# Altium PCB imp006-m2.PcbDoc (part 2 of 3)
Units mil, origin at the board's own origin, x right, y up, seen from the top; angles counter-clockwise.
Board outline 1181.1 x 1515.75 mil, 4 copper layers (Top Layer, Signal Layer 1, Signal Layer 2, Bottom Layer), stack 31.759 mil thick; 78 components, 116 nets, 508 pads, 482 vias.
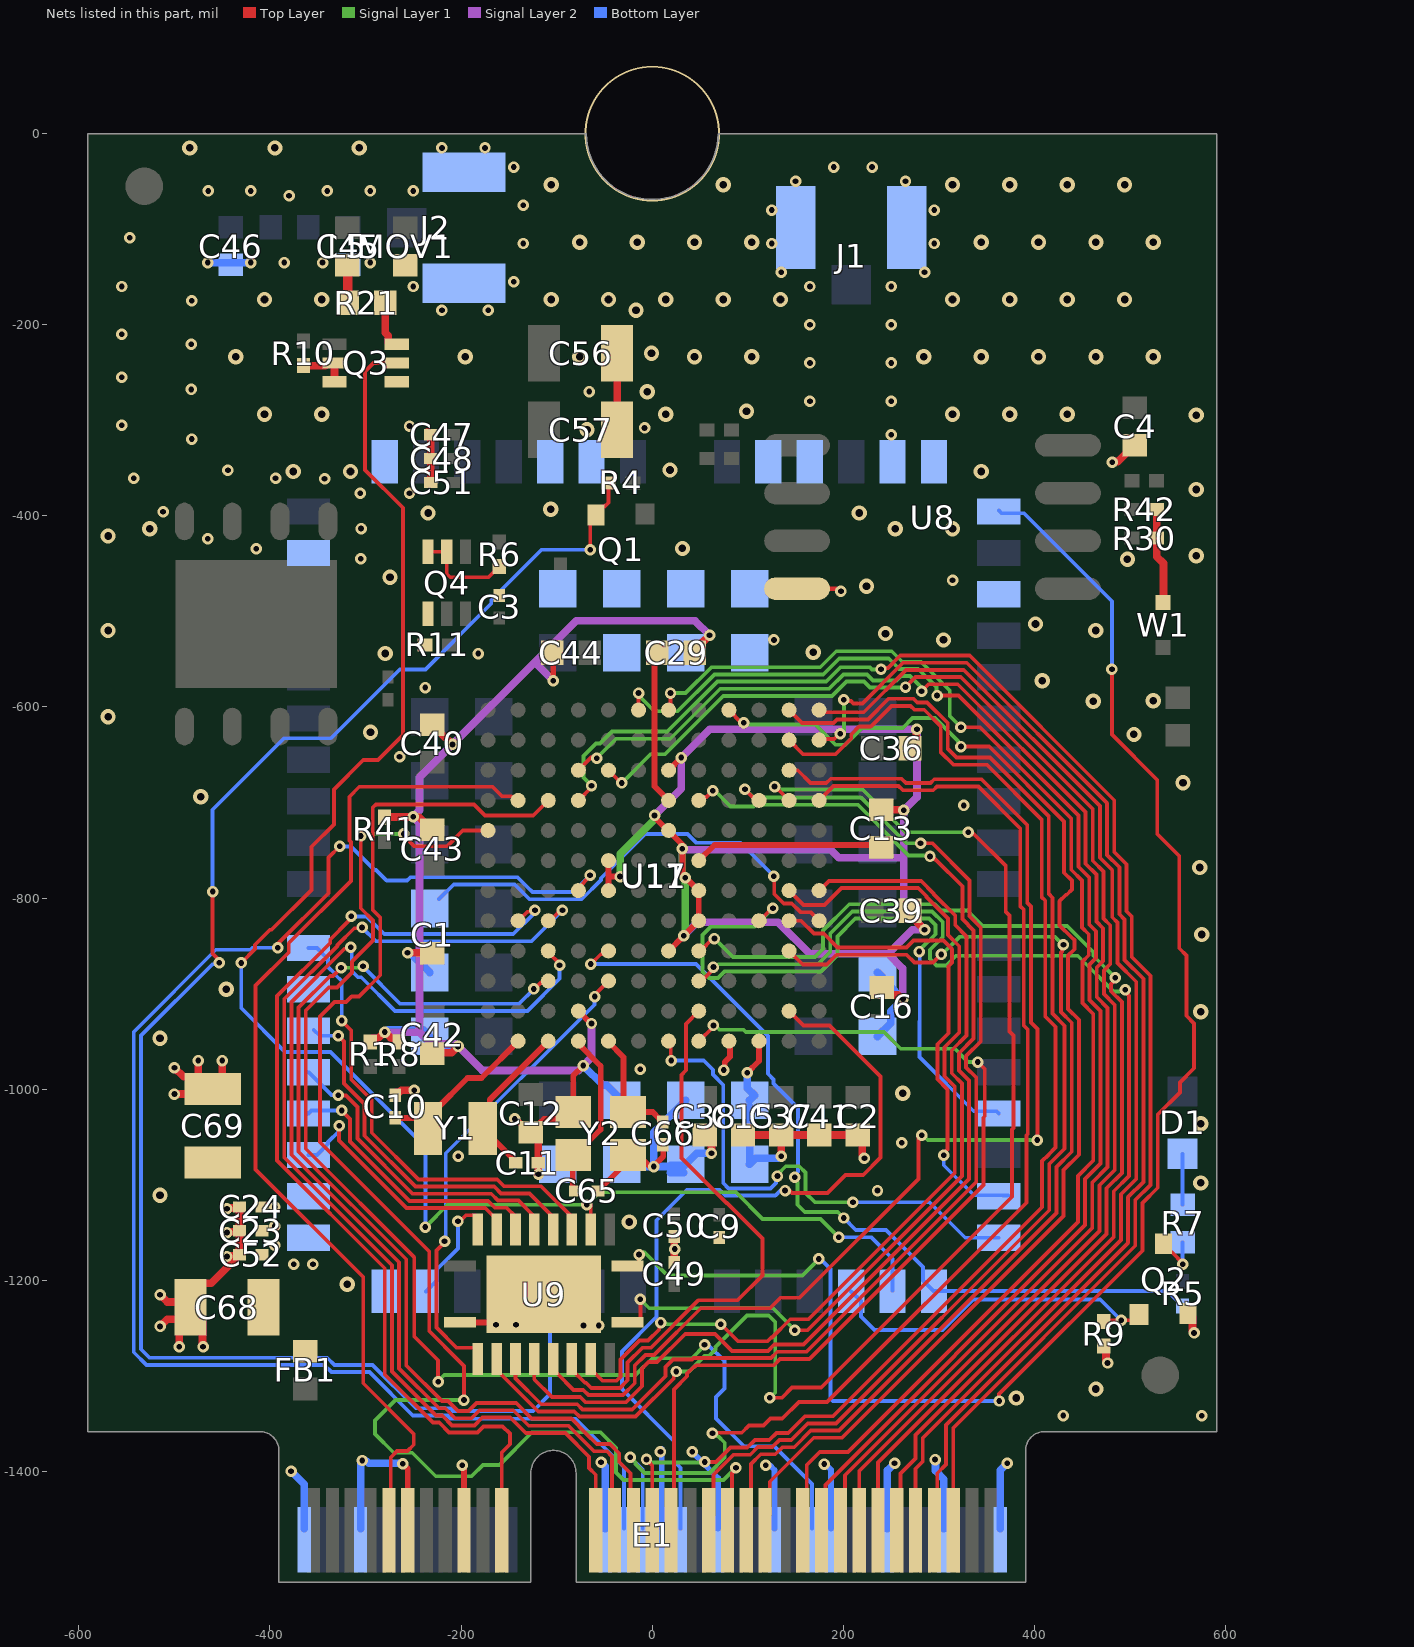
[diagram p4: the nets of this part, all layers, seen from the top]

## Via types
v1: diameter 12, hole 6, Top Layer to Bottom Layer, tented both sides, 300 vias
v2: diameter 16, hole 8, Top Layer to Bottom Layer, tented both sides, 95 vias
v3: diameter 12, hole 6, Top Layer to Signal Layer 1, tented both sides, 86 vias
v4: diameter 141.73, hole 137.8, Top Layer to Bottom Layer, tented both sides, 1 vias

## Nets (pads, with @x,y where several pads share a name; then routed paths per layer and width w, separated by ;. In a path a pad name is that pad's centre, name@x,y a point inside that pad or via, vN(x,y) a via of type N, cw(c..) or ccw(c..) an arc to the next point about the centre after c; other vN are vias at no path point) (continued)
GND: C1.1 C2.1 C3.1 C4.1 C9.1 C10.1 C11.1 C12.1 C13.1 C15.1 C16.1 C23.1 C24.1 C29.1 C36.1 C37.1 C38.1 C39.1 C40.1 C41.1 C42.1 C43.1 C44.1 C45.1 C46.1 C47.1 C48.1 C49.1 C50.1 C51.1 C52.1 C56.1 C57.1 C65.1 C66.1 C68.1 C69.1 E1.1 E1.7 E1.12 E1.18 E1.33 E1.39 E1.45 E1.51 E1.57 E1.63 E1.69 E1.75 J1.1 J1.3 J2.1 J2.3 MOV1.1 Q2.2 Q3.1 Q4.1 R1.2 R8.2 R9.2 R11.2 R30.2 R41.1 R42.2 U8.4 U9.11 U9.21 U11.3 U11.31 U11.48 U11.50 U11.54 U11.55 U11.58 U11.59 U11.61 U11.62 U11.67 U11.68 U11.69 U11.70 U11.71 U11.72 U11.73 U11.74 U11.79 U11.80 U11.81 U11.82 U11.89 U11.90 U11.91 U11.100 U11.101 U11.102 U17.D2 U17.E6 U17.E7 U17.G4 U17.G8 U17.G10 U17.H5 U17.H6 U17.J1 U17.K1 W1.2 Y2.2 Y2.4 | length 6001.5
  Top Layer w5: U8.4@151.57,-476.22 192.8,-476.22 195.54,-478.96 v1(197.43,-478.96)
  Top Layer w6: v1(-260.92,-1391.84) -260.54,-1392.21 -260.54,-1392.51 -255.91,-1397.15 E1.12@-255.91,-1449.8 ; U9.11@-201.14,-1243.98 -143.07,-1243.98 U9.21@-113.54,-1214.46 ; v1(-198.73,-1393.46) -196.85,-1395.34 E1.18@-196.85,-1449.8 ; v1(-143.81,-1031.06) -142.3,-1031.06 -137.3,-1036.06 -136.8,-1036.06 -128.54,-1044.32 C12.1@-128.54,-1044.87 ; C12.1@-127,-1044.87 -126.02,-1044.87 -117.2,-1036.06 -117.2,-1035.08 -113.18,-1031.06 -92.02,-1031.06 Y2.4@-87.09,-1026.13 ; C44.1@-113.23,-546.46 -110.23,-546.46 -103.7,-552.98 v1(-103.7,-572.46) ; Y2.4@-82.54,-1023.55 -82.54,-985.73 v1(-72.05,-975.24) ; U17.D2@-77.28,-918.19 -63.54,-931.93 v1(-63.54,-931.19) ; C65.1@-56.73,-1106.46 -30,-1079.72 -30,-1069.09 -14.43,-1069.09 -2.65,-1080.86 v1(1.46,-1080.86) 1.46,-1080.46 11.46,-1070.46 C66.1@11.46,-1058 ; U17.E6@-45.79,-792.2 -45.79,-777.46 ; U17.E7@-45.79,-760.71 -45.79,-777.46 ; v1(-33.61,-777.46) -45.79,-777.46 ; v1(2.46,-713.46) 2.46,-715.46 16.21,-729.21 U17.G8@17.2,-729.21 17.2,-729.71 32.46,-744.96 31.46,-745.96 v1(31.46,-748.46) 31.58,-748.58 31.58,-775.75 v1(34.49,-778.66) 35.16,-778.66 U17.H6@48.7,-792.2 U17.H5@48.7,-823.7 v1(32.95,-839.45) U17.G4@17.2,-855.2 ; U17.G10@17.2,-666.22 v1(30.46,-652.97) ; v1(74.93,-979.93) 75.85,-979.01 75.85,-971.63 81.46,-966.02 81.46,-950.95 U17.J1@80.2,-949.68 ; v1(99.46,-982.63) 111.69,-970.4 U17.K1@111.69,-949.68
  Top Layer w8: v1(-515,-1248.19) -507.43,-1240.62 -495.82,-1240.62 C68.1@-495,-1239.8 ; v1(-515,-1215) -507.43,-1222.57 -489.01,-1222.57 C68.1@-483.39,-1228.19 ; v1(-500,-1005) -457.11,-1005 -453.11,-1001 C69.1@-454.31,-999.8 ; v1(-500,-977.37) -490.3,-987.07 -469.27,-987.07 C69.1@-460.16,-996.18 ; v1(-495,-1269.5) C68.1@-495,-1239.8 ; v1(-475,-970) -475,-986.44 -476.06,-987.5 -472.3,-987.5 C69.1@-460,-999.8 -452.99,-999.8 C69.1@-450.81,-1001.99 ; v1(-470,-1269.5) -470.65,-1268.85 -470.65,-1240.92 C68.1@-483.39,-1228.19 ; C69.1@-454.31,-996.18 -450,-991.88 v1(-450,-970) ; v1(-445,-1175) -444.23,-1174.23 C52.1@-433.84,-1174.23 ; v1(-445,-1150) -444.23,-1149.23 -432.86,-1149.23 C23.1@-431.81,-1148.19 ; v1(-445,-1125) -444.23,-1124.23 -432.86,-1124.23 C24.1@-431.81,-1123.19 C23.1@-431.81,-1148.19 ; R1.2@-295,-950.39 -295,-949.41 -292.11,-946.52 -286.69,-946.52 -280.36,-940.19 v1(-280,-940.19) -279.64,-940.19 -273.31,-946.52 -267.89,-946.52 -265,-949.41 R8.2@-265,-950.39 ; R41.1@-280,-715.39 -279.67,-715.06 -250.31,-715.06 v1(-250,-714.75) -249.23,-715.52 -243.97,-715.52 -230.98,-728.5 C43.1@-230,-728.5 ; C10.1@-269,-1006.38 -269,-1005.2 -267.09,-1003.3 -264.71,-1003.3 -262.41,-1001 v1(-249,-1001) ; v1(-256,-857.19) -230.68,-857.19 C1.1@-230,-857.87 ; C47.1@-234.7,-312.11 -234.7,-313.09 -232.8,-315 C47.1@-231.81,-315 C48.1@-231.81,-340 C51.1@-231.81,-365 ; C42.1@-230,-962.87 -229.03,-961.9 -209.89,-961.9 v1(-203.18,-955.19) ; C40.1@-230,-618.5 -229.02,-618.5 -221.2,-626.32 -221.2,-627.3 -209.31,-639.19 v1(-209,-639.19) ; C12.1@-127,-1044.87 -119.19,-1052.68 C11.1@-119.19,-1077 -119.09,-1077.09 -119.09,-1088.91 v1(-119,-1089) ; C57.1@-36.61,-310 C56.1@-36.61,-230 ; C49.1@23,-1181.38 C50.1@23,-1154 ; C29.1@44.69,-543.19 52.5,-535.38 52.5,-532.5 v1(60,-525) ; C38.1@55,-1047.87 62,-1054.87 v1(62,-1067) ; C15.1@95,-1047.87 C37.1@135,-1047.87 ; v1(135.05,-1070.01) 135,-1069.96 C37.1@135,-1047.87 ; v1(222.02,-1072.17) 222.02,-1071.09 219.67,-1068.74 219.67,-1052.55 C2.1@215,-1047.87 C41.1@175,-1047.87 C37.1@135,-1047.87 ; C13.1@239.57,-707.37 239.61,-707.42 261.42,-707.42 262.19,-708.19 v1(263.28,-708.19) ; C16.1@240,-893.5 247.81,-901.32 256.84,-901.32 261.2,-905.67 v1(262.28,-905.67) ; C39.1@269.69,-813.19 277.5,-821 277.5,-825.52 v1(284.95,-832.98) ; C36.1@269.69,-643.19 276.23,-636.64 276.23,-623.95 v1(277,-623.19) ; R9.2@472.44,-1268.7 474.87,-1271.13 474.87,-1283.75 476.5,-1285.37 v1(476.5,-1286.46) ; v1(481.28,-343.96) 482.04,-343.19 486.97,-343.19 504.02,-326.14 C4.1@505,-326.14 ; R42.2@527.8,-393.19 R30.2@527.8,-423.19 527.8,-442.57 535,-449.77 W1.2@535,-491.38 ; Q2.2@560.59,-1234.61 565.31,-1239.32 565.31,-1252.29 566.93,-1253.91 v1(566.93,-1255) ; C68.1@-495,-1239.8 C68.1@-483.39,-1228.19 ; C68.1@-483.39,-1228.19 -483.39,-1215.59 -470.65,-1202.86 -461.48,-1202.86 -434.7,-1176.08 -434.7,-1175.09 C52.1@-433.84,-1174.23 ; C52.1@-433.84,-1174.23 -432.8,-1173.19 C52.1@-431.81,-1173.19 C23.1@-431.81,-1148.19
  Signal Layer 2 w8: v1(-280,-940.19) -243.54,-940.19 ; v1(-256,-857.19) -243.54,-857.19 ; v1(-203.18,-955.19) -205.75,-952.61 -231.12,-952.61 -243.54,-940.19 ; v1@-203,-955.19 -177.88,-980.31 -77.12,-980.31 v1(-72.05,-975.24) -63.54,-966.73 v1(-63.54,-931.19) ; v1(-103.7,-572.46) -122.98,-553.17 ; v1(2.46,-713.46) 30.46,-685.46 v1(30.46,-652.97) 60.24,-623.19 v1(277,-623.19) 277,-694.46 v1(263.28,-708.19) 263.28,-757.83 ; v1(32.95,-839.45) 47.19,-825.21 131.63,-825.21 164.71,-858.3 246.89,-858.3 ; v1(34.49,-778.66) 34.49,-777.58 31.46,-774.54 v1(31.46,-748.46) 32.22,-749.22 35.05,-749.22 35.12,-749.29 186.67,-749.29 195.21,-757.83 263.28,-757.83 ; v1(60,-525) 44.69,-509.69 -79.5,-509.69 -122.98,-553.17 ; v1(262.28,-905.67) 262.28,-873.69 246.89,-858.3 ; v1@283.64,-831.67 263.28,-811.3 263.28,-757.83 ; v1(284.95,-832.98) 272.21,-832.98 246.89,-858.3 ; -243.54,-940.19 -243.54,-857.19 ; -243.54,-857.19 -243.54,-721.44 -250,-714.98 v1(-250,-714.75) -250,-714.52 -243.54,-708.07 -243.54,-673.73 v1(-209,-639.19) -122.98,-553.17
  Signal Layer 1 w8: v1(-33.61,-777.46) -33.61,-753.68 1.69,-718.38 1.69,-714.22 v1(2.46,-713.46) ; v1@30.69,-747.69 v1(31.46,-748.46) 31.46,-774.54 34.49,-777.58 v1(34.49,-778.66) 34.49,-836.83 32.95,-838.37 v1(32.95,-839.45)
  Bottom Layer w6: v1(8.62,-1379.19) 8.62,-1377.36 9.84,-1376.14 E1.39@9.84,-1459.65 ; U11.70@19.11,-1078.58 U11.70@34.92,-1078.58 ; v1(42,-1379.19) 42,-1379.62 48.08,-1385.7 48.08,-1385.81 68.9,-1406.63 E1.45@68.9,-1459.65 ; v1(118.89,-1393.48) 123.09,-1393.48 127.95,-1398.35 E1.51@127.95,-1459.65 ; v1(180,-1392.2) 181.01,-1392.2 187.01,-1398.2 E1.57@187.01,-1459.65
  Bottom Layer w8: v1(-465,-135) v1(-420,-135) ; v1(-377.91,-1399.69) -364.17,-1413.42 E1.1@-364.17,-1459.65 ; E1.7@-305.12,-1459.65 -305.12,-1389.03 -304.54,-1388.46 v1(-303.54,-1388.46) ; v1@-303.23,-1389.22 -298.61,-1389.22 -296.37,-1391.46 -261.3,-1391.46 v1(-260.92,-1391.84) ; v1(-280,-940.19) -278.92,-940.19 -276.6,-937.87 -239.65,-937.87 U11.73@-232.8,-944.72 -222.33,-955.19 v1(-203.18,-955.19) ; v1(-256,-857.19) -255.23,-857.95 -252.64,-857.95 U11.74@-232.8,-877.8 ; v1(-72.05,-975.24) -51.32,-995.97 -47.7,-995.97 U11.91@-32.01,-1011.65 ; v1(-53.54,-1390.3) -49.21,-1394.63 E1.33@-49.21,-1459.65 ; U11.71@-32.01,-1078.58 -29.73,-1080.86 v1(1.46,-1080.86) ; U11.70@19.15,-1087.52 U11.70@32.68,-1087.52 ; U11.90@34.92,-1011.65 1.46,-1045.11 v1(1.46,-1080.86) ; v1(62,-1067) 46.5,-1067 U11.70@34.92,-1078.58 32.64,-1080.86 v1(1.46,-1080.86) ; v1(99.46,-982.63) 99.46,-998.97 107,-1006.5 U11.89@101.85,-1011.65 ; U11.89@101.89,-1018.31 101.89,-1078.54 U11.69@101.85,-1078.58 108.35,-1072.08 131.9,-1072.08 133.97,-1070.01 v1(135.05,-1070.01) ; U11.68@235.7,-944.72 249.64,-930.79 249.64,-918.32 v1(262.28,-905.67) 246.43,-889.82 246.43,-888.52 U11.67@235.7,-877.8 ; E1.63@246.06,-1459.65 246.06,-1398.98 v1(253.61,-1391.43) ; v1(295.96,-1387.45) 296.46,-1387.95 296.46,-1399.33 305.12,-1407.99 E1.69@305.12,-1459.65 ; E1.75@364.17,-1459.65 364.17,-1398.74 v1(371.46,-1391.46)
  other v1: 430,-1341.46 575,-1341.69 -72,-1247.19 -56,-1247.19 -163.43,-1246.46 -142.43,-1246.46 23.55,-1167.27 235.7,-1106 -202.87,-1070.13 261.2,-1055.84 -12.43,-978.96 326,-703 -264.36,-652.01 -237.4,-579.64 -182.12,-544.08 127.36,-529.83 314.22,-467.32 -305,-445 -414.22,-434.41 -465,-423.9 -304.69,-413.29 -511.87,-395.59 -305.43,-376.46 -254,-376.22 -542.5,-360.66 -394.15,-360.66 -342.82,-361.07 -443.95,-352.16 -481.85,-319.65 250,-315 -8,-308 -254,-306 -555,-305.12 165,-280 250,-280 -66,-270 -482.34,-267.67 -555,-255 165,-240 250,-240 -482.34,-220.31 -555,-210 165,-200 250,-200 -220,-185 -171.54,-185 -481.85,-175 -555,-160 -250,-160 165,-160 250,-160 -145,-155 135,-145 285,-145 -385,-135 -345,-135 -295,-135 -135,-115 125,-115 295,-115 -546.77,-108.96 125,-80 295,-80 -135,-75 -380,-65 -464.59,-60 -420,-60 -340,-60 -295,-60 -250,-60 150,-50 265,-50 -145,-35 190,-35 230,-35 -220,-15 -175,-15
  other v2: 381,-1323 464.25,-1313.62 -319.17,-1204.02 -23.98,-1138.96 -515,-1110.87 574,-1098 574,-1036 262.01,-1004.23 -515,-946.52 574,-919 -445.77,-895.25 575,-838 573,-768 -472.3,-693.86 555.4,-679.34 504.02,-628.7 -294.84,-626.32 -569.38,-610.33 461.5,-593.88 524.25,-593.62 408,-572.46 -279.32,-544.08 168.59,-542.76 304.84,-529.83 244.1,-523.19 -569.38,-519.93 463.99,-520 401,-513.17 224.25,-473.62 -274.42,-464.22 497.2,-445.52 569.38,-441.81 31.58,-434.08 -569.38,-421.13 -525.75,-413.62 254.25,-413.62 314.25,-413.62 -234.54,-397.07 216.54,-397.07 -106.04,-393.19 569.38,-372.5 -375.75,-353.62 -315.75,-353.62 344.25,-353.62 18.53,-352.03 -68.15,-310 569.38,-294.57 -405.75,-293.62 -345.75,-293.62 14.25,-293.62 314.25,-293.62 374.25,-293.62 434.25,-293.62 98.63,-290.59 -5.21,-270 -435.75,-233.62 -195.75,-233.62 -75.75,-233.62 44.25,-233.62 104.25,-233.62 284.25,-233.62 344.25,-233.62 404.25,-233.62 464.25,-233.62 524.25,-233.62 -0.76,-229.99 -17.03,-185 -405.75,-173.62 -345.75,-173.62 -105.75,-173.62 -45.75,-173.62 14.25,-173.62 74.25,-173.62 134.25,-173.62 314.25,-173.62 374.25,-173.62 434.25,-173.62 494.25,-173.62 -75.75,-113.62 -15.75,-113.62 44.25,-113.62 104.25,-113.62 344.25,-113.62 404.25,-113.62 464.25,-113.62 524.25,-113.62 -105.75,-53.62 74.25,-53.62 314.25,-53.62 374.25,-53.62 434.25,-53.62 494.25,-53.62 -484.03,-15 -394.83,-15 -306.52,-15
  other v4: 0,0
LED_GREEN: E1.38 U17.L11 | length 1369
  Top Layer w4: v3(-6,-1387.37) -3.56,-1387.37 -3.56,-1390.15 0,-1393.71 E1.38@0,-1449.8 ; v3(55,-1390) 66.67,-1390 81.78,-1374.89 99.46,-1374.89 107.38,-1366.98 122.51,-1366.98 129.93,-1359.57 142.33,-1359.57 159.7,-1342.19 189.23,-1342.19 408,-1123.42 408,-1075.19 414.5,-1068.69 414.5,-1068.56 422,-1061.06 422,-934.65 411.29,-923.94 411.29,-802.67 407.5,-798.88 407.5,-717.57 350.39,-660.46 315.13,-660.46 301.82,-647.14 301.82,-620.08 284.57,-602.83 274.27,-602.83 270.27,-598.83 250.4,-598.83 228.75,-620.48 216.54,-620.48 208.31,-628.7 208.31,-632.87 191.72,-649.46 157.92,-649.46 U17.L11@143.19,-634.72
  Signal Layer 1 w4: v3(-6,-1387.37) -2.68,-1390.69 54.31,-1390.69 v3(55,-1390)
LED_RED: E1.44 U17.L12 | length 1294.9
  Top Layer w4: E1.44@59.06,-1449.8 63.95,-1444.91 63.95,-1403.33 84.88,-1382.39 102.57,-1382.39 110.48,-1374.48 125.62,-1374.48 133.04,-1367.07 145.43,-1367.07 162.81,-1349.69 192.34,-1349.69 415.5,-1126.53 415.5,-1078.3 431.5,-1062.3 431.5,-933.55 418.79,-920.83 418.79,-799.56 415,-795.77 415,-714.46 353.5,-652.96 318.24,-652.96 309.32,-644.04 309.32,-616.97 287.67,-595.33 277.38,-595.33 273.38,-591.33 247.29,-591.33 225.64,-612.98 193.26,-612.98 189.63,-616.6 156.56,-616.6 U17.L12@143.19,-603.23
MCU_AP_READY: R5.2 U11.19 U17.E4 | length 880.7
  Top Layer w4: v1(-64.22,-868.97) -64.15,-868.97 -53.9,-858.71 -52.48,-858.71 -48.97,-855.2 U17.E4@-45.79,-855.2
  Signal Layer 1 w4: v1(149,-1092) 149,-1094.16 152.13,-1097.3 152.13,-1120.88 159.57,-1128.31 194.11,-1128.31 v1(200.5,-1134.7)
  Bottom Layer w4: v1@-64.16,-868.98 45.64,-868.98 121.09,-944.43 121.09,-983.75 127.03,-989.69 127.03,-993.84 152.7,-1019.5 152.7,-1086.14 ; v1(200.5,-1134.7) 212.96,-1147.18 244.65,-1147.18 283.39,-1185.92 283.39,-1200.09 294.3,-1211 539.2,-1211 R5.2@555,-1226.8
MCU_CTS_3V3: U9.15 U17.H9 | length 1253
  Top Layer w4: U9.15@-123.39,-1282.37 -123.39,-1303.53 -104.77,-1322.14 -75.34,-1322.14 -69.95,-1327.52 -27.54,-1327.52 -10.76,-1310.74 -10.76,-1292.26 -4.03,-1285.52 4.97,-1285.52 34.53,-1255.96 65.64,-1255.96 83.44,-1273.76 121.07,-1273.76 127.64,-1267.19 158.17,-1267.19 331.5,-1093.86 331.5,-990.76 320.96,-980.22 320.96,-962.27 336.29,-946.94 336.29,-833.73 324.5,-821.94 324.5,-787.5 296.49,-759.49 295.96,-759.49 292.82,-756.35 v3(290.65,-756.35) ; U17.H9@48.7,-697.72 51.88,-697.72 55.31,-694.29 56.89,-694.29 v3(63.46,-687.72)
  Signal Layer 1 w4: v3(63.46,-687.72) 65.53,-687.72 81.78,-703.97 105.9,-703.97 107.61,-702.26 215.17,-702.26 268.21,-755.3 289.61,-755.3 v3(290.65,-756.35)
MCU_DTR_3V3: U9.12 U17.E3 | length 499.1
  Top Layer w4: v1(-217.3,-1159) -217.3,-1160.3 -225.75,-1168.75 -225.75,-1249.4 -204.65,-1270.5 -185.95,-1270.5 -182.44,-1274.01 U9.12@-182.44,-1282.37 ; v1(-60.03,-903.02) -60.03,-900.93 U17.E3@-45.79,-886.69
  Bottom Layer w4: v1(-217.3,-1159) -216,-1157.7 -216,-1067 -60.51,-911.51 -60.51,-903.51 v1(-60.03,-903.02)
MCU_PSM_IND: U9.20 U17.M6 | length 903.2
  Top Layer w4: U9.20@-25.94,-1243.98 -14.41,-1243.98 -12.43,-1242 v3(-12.43,-1219.84) ; v3(149.25,-1252.19) 162.56,-1252.19 324,-1090.75 324,-993.87 313.46,-983.33 313.46,-959.16 328.79,-943.83 328.79,-840.01 317,-828.22 317,-818.3 294.5,-795.79 294.5,-795.01 281.53,-782.04 184.85,-782.04 U17.M6@174.69,-792.2
  Signal Layer 1 w4: v3(-12.43,-1219.84) -3.09,-1229.19 126.25,-1229.19 v3(149.25,-1252.19)
MCU_RADIO_PWRON: U11.15 U17.K5 | length 683.8
  Top Layer w4: U17.K5@111.69,-823.7 112.42,-823.7 125.6,-810.52 v3(126.32,-810.52)
  Signal Layer 1 w4: v3(126.32,-810.52) 106.97,-829.87 61.32,-829.87 52.5,-838.69 52.5,-876.95 59.24,-883.69 68.76,-883.69 75.76,-876.69 176.54,-876.69 193.82,-859.41 193.82,-840.06 212.4,-821.48 289.71,-821.48 296.45,-828.21 296.45,-837.74 279.29,-854.9 v1(279.29,-855.97)
  Bottom Layer w4: v1(279.29,-855.97) 279.97,-856.65 279.97,-928.31 279.5,-928.77 279.5,-966.18 336.38,-1023.06 360.3,-1023.06 U11.15@362.67,-1025.43
MCU_RADIO_RST: U11.17 U17.L5 | length 507.7
  Top Layer w4: U17.L5@143.19,-823.7 155.77,-823.7 169.15,-837.07 179.41,-837.07 194.03,-851.69 266.24,-851.69 273.45,-844.47 284.73,-844.47 304.84,-844.48 313.79,-853.42 313.79,-867.47 310,-871.26 310,-941.4 298.46,-952.95 298.46,-989.54 309,-1000.08 309,-1063.02 305,-1067.02 v1(305,-1069.19)
  Bottom Layer w4: v1(305,-1069.19) 305,-1079.45 336.38,-1110.83 367.21,-1110.83 367.49,-1111.1 U11.17@372.3,-1111.1
MCU_RADIO_STATUS: U9.18 U17.L6 | length 992.2
  Top Layer w4: U9.18@-64.33,-1282.37 -64.33,-1293.59 -60.82,-1297.1 -59.94,-1297.1 -52.01,-1305.02 -37.28,-1305.02 -33.26,-1301.01 -33.26,-1282.94 -13.35,-1263.02 -4.35,-1263.02 7.31,-1251.35 7.31,-1245.7 v3(8.85,-1244.17) ; v3(71.82,-1245.87) 89.63,-1263.69 120.53,-1263.69 124.53,-1259.69 125.49,-1259.69 144.49,-1240.69 163.45,-1240.69 316.5,-1087.64 316.5,-996.98 305.96,-986.43 305.96,-956.05 321.29,-940.72 321.29,-850.31 309.5,-838.52 309.5,-821.4 287,-798.9 287,-798.12 278.42,-789.54 198.08,-789.54 180.42,-807.19 158.18,-807.19 U17.L6@143.19,-792.2
  Signal Layer 1 w4: v3(8.85,-1244.17) 10.38,-1245.7 15.01,-1245.7 15.19,-1245.87 v3(71.82,-1245.87)
MCU_RI_3V3: U9.17 U17.H2 | length 597.5
  Top Layer w4: U9.17@-84.02,-1282.37 -84.02,-1293.59 -70.46,-1307.14 -69.12,-1307.14 -63.74,-1312.52 -33.76,-1312.52 -25.76,-1304.53 -25.76,-1286.05 -10.24,-1270.52 -1.25,-1270.52 48.59,-1220.69 89.46,-1220.69 115.22,-1194.93 115.22,-1156.02 78.18,-1118.99 77.62,-1118.99 30.5,-1071.86 30.5,-985.02 35.33,-980.19 35.33,-931.56 U17.H2@48.7,-918.19
MCU_RTS_3V3: U9.16 U17.L10 | length 1293.1
  Top Layer w4: U9.16@-103.7,-1282.37 -103.7,-1293.59 -100.19,-1297.1 -99.81,-1297.1 -82.27,-1314.64 -72.23,-1314.64 -66.85,-1320.02 -30.65,-1320.02 -18.26,-1307.64 -18.26,-1289.15 -7.13,-1278.02 1.86,-1278.02 50.69,-1229.19 123.21,-1229.19 134.21,-1218.19 154.13,-1218.19 278.5,-1093.82 278.5,-1051.69 v3(282,-1048.19) ; U17.L10@143.19,-666.22 152.25,-666.22 165.72,-679.69 182.11,-679.69 186.73,-675.06 260.85,-675.06 265.48,-679.69 291.02,-679.69 295.02,-675.69 344.41,-675.69 392.5,-723.78 392.5,-805.09 396.29,-808.88 396.29,-930.15 403,-936.87 v3(403,-1053.19)
  Signal Layer 1 w4: v3(282,-1048.19) 283.34,-1048.19 288.34,-1053.19 v3(403,-1053.19)
MCU_RXD_3V3: U9.14 U17.K9 | length 1245.2
  Top Layer w4: U9.14@-143.07,-1282.37 -142.98,-1282.46 -142.98,-1302.76 -116.1,-1329.64 -78.44,-1329.64 -73.06,-1335.02 -20.91,-1335.02 13.75,-1300.37 13.75,-1290.56 21.62,-1282.69 41.76,-1282.69 43.2,-1281.26 124.18,-1281.26 130.74,-1274.69 161.27,-1274.69 339,-1096.96 339,-987.66 328.46,-977.11 328.46,-965.37 343.79,-950.04 343.79,-830.63 332,-818.84 332,-781.43 293.12,-742.55 v3(280.8,-742.55) ; v3(97,-686.19) 108.53,-697.72 U17.K9@111.69,-697.72
  Signal Layer 1 w4: v3(97,-686.19) 97.3,-686.19 105.87,-694.76 218.28,-694.76 266.07,-742.55 v3(280.8,-742.55)
MCU_TXD_3V3: U9.13 U17.L9 | length 1431.4
  Top Layer w4: U9.13@-162.76,-1282.37 -162.76,-1293.59 -119.2,-1337.14 -81.55,-1337.14 -76.17,-1342.52 -17.34,-1342.52 22.46,-1302.73 v3@22.46,-1299.59 ; v3(123.09,-1322.76) 135.71,-1322.76 146.28,-1312.19 176.81,-1312.19 376.5,-1112.5 376.5,-1042.21 378,-1040.71 378,-943.69 373.79,-939.47 373.79,-818.2 370,-814.41 370,-766.28 336.3,-732.58 332.17,-732.58 v3(330.64,-731.05) ; 133.19,-687.72 U17.L9@143.19,-697.72
  Signal Layer 1 w4: v3(25.25,-1295.32) 38.3,-1295.32 54.66,-1278.96 59.54,-1278.96 66.28,-1272.22 66.28,-1269.73 99.32,-1236.69 121.93,-1236.69 128.66,-1243.43 128.66,-1317.18 v3(123.09,-1322.76) ; v3(128,-683.26) 128,-683.85 130.34,-686.19 220.31,-686.19 265.18,-731.05 v3(330.64,-731.05)
MCU_USB_BOOT: U11.75 U17.M5 | length 487.9
  Top Layer w4: v1(127.23,-777.15) 127.64,-777.56 127.64,-795.57 137.65,-805.58 145.96,-805.58 155.07,-814.69 165.68,-814.69 U17.M5@174.69,-823.7
  Bottom Layer w4: U11.75@-223.01,-801.07 -207.61,-785.68 -143.91,-785.68 -128.44,-801.15 -73.7,-801.15 -53.5,-780.95 -53.5,-779.15 -7.33,-732.97 36.78,-732.97 45.78,-741.97 92.05,-741.97 v1(127.23,-777.15)
MCU_W_DISABLE: U11.18 U17.G1 | length 541.6
  Top Layer w4: U17.G1@17.2,-949.68 19.42,-951.9 19.42,-970.79 20,-970.21 v1(20,-970)
  Signal Layer 1 w4: v1(131.03,-1090.89) 131.03,-1089.24 139.78,-1080.5 153.76,-1080.5 160.5,-1087.24 160.5,-1108.49 170.2,-1118.19 v1(210,-1118.19)
  Bottom Layer w4: v1(20,-970) 53.85,-970 63.43,-979.58 63.43,-984.69 74.3,-995.56 74.3,-1098.18 79.88,-1103.77 123.81,-1103.77 129.37,-1098.2 129.5,-1098.08 129.5,-1092.42 v1(131.03,-1090.89) ; v1(210,-1118.19) 290.31,-1118.19 327.47,-1155.35 U11.18@362.67,-1155.35
MODULE_CTS: U9.6 U11.36 | length 331.8
  Top Layer w4: v1(-328.5,-1006.19) -328.14,-1006.55 -320.39,-1006.55 -308.5,-1018.44 -308.5,-1051.68 -250.87,-1109.31 -168.44,-1109.31 -161.29,-1116.46 -140.04,-1116.46 -123.39,-1133.11 U9.6@-123.39,-1146.54
  Bottom Layer w4: U11.36@-359.77,-982.13 -335.74,-1006.15 -329.04,-1006.15 -329,-1006.19 v1(-328.5,-1006.19)
MODULE_DCD: U11.38
MODULE_DTR: U9.9 U11.30 | length 123.4
  Top Layer w4: v1(-203.36,-1138.03) -201.2,-1138.03 -194.98,-1131.81 -185.95,-1131.81 -182.44,-1135.32 U9.9@-182.44,-1146.54
  Bottom Layer w4: U11.30@-236.74,-1211.46 -224.96,-1199.68 -224.96,-1188.18 -203.36,-1166.59 v1(-203.36,-1138.03)
MODULE_NETLIGHT: Q2.1 R9.1 U11.21 | length 371.2
  Top Layer w4: R9.1@472.44,-1243.11 473.76,-1241.79 v1(490.75,-1241.79) 503.21,-1241.79 Q2.1@509.41,-1235.59
  Bottom Layer w4: U11.21@208.15,-1211.46 218.36,-1221.68 218.36,-1237.75 232.46,-1251.84 303.69,-1251.84 335.69,-1219.84 468.81,-1219.84 v1(490.75,-1241.79)
MODULE_PSM_IND: U9.1 U11.1 | length 1672.7
  Top Layer w4: U9.1@-25.94,-1184.93 -17.27,-1184.93 -13.76,-1181.42 v3(-13.76,-1172.96) ; v1(363,-1326.19) 363,-1319.04 513,-1169.04 513,-1119.14 529,-1103.14 529,-1026.5 552.13,-1003.37 552.13,-992.83 567,-977.96 567,-931.09 559,-923.09 559,-859.91 551.5,-852.41 551.5,-755.98 528.5,-732.98 528.5,-676.38 480.98,-628.86 v1(480.98,-560.64)
  Signal Layer 1 w4: v3(-13.76,-1172.96) -11.59,-1172.96 -9.2,-1170.57 -8.06,-1170.57 16.13,-1194.76 157.12,-1194.76 v1(174.38,-1177.5)
  Bottom Layer w4: v1(174.38,-1177.5) 175.99,-1177.5 186.54,-1188.06 186.54,-1323.85 188.88,-1326.19 v1(363,-1326.19) ; U11.1@362.68,-394.57 365.45,-397.34 388.97,-397.34 480.98,-489.35 v1(480.98,-560.64)
MODULE_RING: U9.4 U11.39 | length 484.7
  Top Layer w4: v1(-324.92,-928.08) -324.92,-928.49 -314.89,-938.51 -314.89,-989.85 -293.5,-1011.24 -293.5,-1045.47 -244.66,-1094.31 -162.22,-1094.31 -155.08,-1101.46 -116.31,-1101.46 -84.02,-1133.75 U9.4@-84.02,-1146.54
  Bottom Layer w4: U11.39@-359.77,-852.2 -350.91,-852.2 -339.13,-863.98 -339.13,-871.95 -331.63,-879.45 -331.63,-880.11 -324.92,-886.82 v1(-324.92,-928.08)
MODULE_RTS: U9.5 U11.37 | length 389.6
  Top Layer w4: v1(-328.5,-944.03) -322.39,-950.14 -322.39,-993.95 -301,-1015.34 -301,-1048.57 -247.76,-1101.81 -165.33,-1101.81 -158.19,-1108.96 -128.29,-1108.96 -103.7,-1133.54 U9.5@-103.7,-1146.54
  Bottom Layer w4: U11.37@-354.11,-937.87 -347.95,-944.03 v1(-328.5,-944.03)
MODULE_RXD: U9.8 U11.34 | length 274.8
  Top Layer w4: v1(-327.63,-1038.19) -327.63,-1053.76 -257.08,-1124.31 -174.65,-1124.31 -167.15,-1131.81 -166.27,-1131.81 -162.76,-1135.32 U9.8@-162.76,-1146.54
  Bottom Layer w4: U11.34@-359.77,-1068.74 -350.91,-1068.74 -339.13,-1056.96 -339.13,-1055.32 -327.24,-1043.43 -327.24,-1038.58 v1(-327.63,-1038.19)
MODULE_STATUS: Q3.2 U9.3 U11.20 | length 1732.4
  Top Layer w4: v1(-430.08,-867.84) -415.52,-853.28 -415.52,-848.75 -399.78,-833.01 -398.1,-833.01 -356.5,-791.41 -356.5,-746.19 -333.15,-722.84 -333.15,-686.25 -302.34,-655.43 -287.03,-655.43 -260.92,-629.32 -260.92,-391.58 -300.43,-352.07 -300.43,-248.93 -291.5,-240 Q3.2@-267.52,-240 ; v3(-68.54,-1120.88) -68.06,-1120.88 -68,-1120.81 v3@-64.33,-1124.48 ; U9.3@-64.33,-1146.54 v3@-64.33,-1121.6
  Signal Layer 1 w4: v1(-237.4,-1144.19) -214.09,-1120.88 v3(-68.54,-1120.88) -55.36,-1107.69 87.35,-1107.69 115.48,-1135.81 176.13,-1135.81 v1(195.08,-1154.77)
  Bottom Layer w4: v1(-430.08,-867.84) -430.08,-914.94 -384.1,-960.92 -336.78,-960.92 -237.4,-1060.3 v1(-237.4,-1144.19) ; v1(195.08,-1154.77) 228.82,-1154.77 251.46,-1177.41 U11.20@251.46,-1210.51
MODULE_TXD: U9.7 U11.35 | length 291.1
  Top Layer w4: v1(-325,-1022.19) -316.13,-1031.06 -316.13,-1054.66 -253.98,-1116.81 -171.54,-1116.81 -164.4,-1123.96 -152.41,-1123.96 -143.07,-1133.3 U9.7@-143.07,-1146.54
  Bottom Layer w4: U11.35@-359.77,-1025.43 -356.52,-1022.19 v1(-325,-1022.19)
MODULE_UART3_TXD: Q1.2 R4.2 U11.27 | length 1763.9
  Top Layer w4: v1(-460,-793.19) -460,-858.1 -453.5,-864.6 -453.5,-867.19 v1(-453.08,-867.61) ; v1(-64.87,-435.46) -64.87,-406.48 -65.46,-405.88 Q1.2@-58.62,-399.04 -58.62,-397.07 -51.76,-390.21 -49.79,-390.21 -45.84,-386.27 R4.2@-45.84,-365.46
  Bottom Layer w4: v1(-460,-793.19) -460,-707.49 -385.29,-632.78 -336.31,-632.78 -264.17,-560.64 -237.3,-560.64 -168.5,-491.85 -168.5,-488.02 -115.94,-435.46 v1(-64.87,-435.46) ; v1(-453.08,-867.61) -454.61,-869.14 -460.27,-869.14 -535,-943.88 -535,-1272.09 -526.09,-1281 -340.01,-1281 -332.51,-1288.5 -292.85,-1288.5 -247.5,-1333.85 -211.23,-1333.85 -208.52,-1336.57 -124.52,-1336.57 -106.81,-1318.86 U11.27@-106.81,-1211.46
NetC13_2: C13.2 U17.H7 | length 198.6
  Top Layer w6: U17.H7@48.7,-760.71 65.05,-744.36 237.19,-744.36 C13.2@239.57,-746.74
NetC23_2: C23.2 C24.2 C52.2 C68.2 C69.2 FB1.2 U11.32 U11.33
  other v1: -375,-1183.19 -355,-1183.19 -395,-1163.19 -395,-1143.19 -395,-1123.19
NetC29_2: C29.2 U17.G9 | length 158.9
  Top Layer w6: C29.2@6.14,-546.46 2.46,-550.14 2.46,-682.97 U17.G9@17.2,-697.72
NetD1_K: D1.K R7.1 | length 53.3
  Bottom Layer w4: R7.1@555,-1120.78 D1.K@555,-1067.48
NetL5_1: L5.1 R21.1 | length 39.4
  Top Layer w10: L5.1@-319,-137.68 -318.68,-138 R21.1@-318.68,-177
NetQ2_3: Q2.3 R7.2 | length 53.9
  Top Layer w4: Q2.3@535,-1161.77 535,-1163.74 541.86,-1170.6 543.83,-1170.6 555,-1181.77 v1(555,-1183.19)
  Bottom Layer w4: v1(555,-1183.19) R7.2@555,-1160.15
NetQ3_3: Q3.3 R21.2 | length 52.2
  Top Layer w8: R21.2@-279.32,-177 -279.32,-208.52 -276.32,-211.52 -276.32,-218.41 -274.41,-220.31 Q3.3@-267.52,-220.31
NetQ3_5: Q3.5 Q3.6 R10.2 | length 53.4
  Top Layer w8: R10.2@-365,-242.8 -342.17,-242.8 -339.37,-240 Q3.5@-332.48,-240 Q3.6@-332.48,-259.68
NetQ4_5: Q4.5 Q4.6 R6.2 | length 104.6
  Top Layer w4: Q4.6@-234.68,-437.52 Q4.5@-215,-437.52 -215,-460.57 -211.35,-464.22 -171.43,-464.22 -165.87,-458.67 -164.89,-458.67 -160,-453.78 R6.2@-160,-452.8
OPTO_BIAS: E1.50 U17.J12 | length 1330.1
  Top Layer w4: U17.J12@80.2,-603.23 93.57,-616.6 v3(95.71,-616.6) ; E1.50@118.11,-1449.8 123,-1444.91 123,-1410.71 169.02,-1364.69 198.55,-1364.69 430.5,-1132.74 430.5,-1084.51 446.5,-1068.51 446.5,-927.33 435.2,-916.03 435.2,-860.11 441.79,-853.51 441.79,-843.99 438.5,-840.7 426.29,-828.49 426.29,-803.19 433.03,-796.45 433.74,-796.45 439.13,-791.06 439.13,-781.53 431,-773.4 431,-719.85 352.6,-641.46 v3(323,-641.46)
  Signal Layer 1 w4: v3(95.71,-616.6) 97.3,-618.19 170.63,-618.19 192.05,-639.6 201.57,-639.6 219.35,-621.83 262.1,-621.83 272.24,-611.69 296.05,-611.69 319.92,-635.56 319.92,-636.22 323,-639.29 v3(323,-641.46)
OPTO_IN: E1.48 U17.L4 | length 1096.7
  Top Layer w4: E1.48@98.43,-1449.8 103.32,-1444.91 103.32,-1392.26 113.59,-1381.98 128.73,-1381.98 136.14,-1374.57 148.54,-1374.57 165.92,-1357.19 195.45,-1357.19 423,-1129.64 423,-1081.4 439,-1065.4 439,-930.44 427.7,-919.13 427.7,-857 428.76,-855.94 428.76,-850.28 v3(430.29,-848.75) ; U17.L4@143.19,-855.2 157.56,-869.57 182.55,-869.57 192.93,-859.19 266.24,-859.19 274.53,-867.47 293.71,-867.47 v3(302.29,-858.89)
  Signal Layer 1 w4: v3(302.29,-858.89) 303,-858.89 321.39,-840.51 421.56,-840.51 429.8,-848.75 v3(430.29,-848.75)
OSC_26M_IN: C65.2 U17.D1 Y2.1 | length 180.8
  Top Layer w6: C65.2@-80.35,-1106.46 -83.13,-1103.68 -83.13,-1069.42 Y2.1@-82.54,-1068.83 -80.57,-1068.83 -54,-1042.25 -54,-975.61 -77.28,-952.32 U17.D1@-77.28,-949.68
OSC_26M_OUT: C66.2 U17.E1 Y2.3 | length 126.6
  Top Layer w6: U17.E1@-45.79,-949.68 -45.79,-950.65 -30,-966.44 -30,-1023.82 0.44,-1023.82 7.11,-1030.49 8.09,-1030.49 11,-1033.39 C66.2@11,-1034.38
OSC_32K_IN: C10.2 U17.B1 Y1.1 | length 182.9
  Top Layer w6: C10.2@-269,-1030 -238.54,-1030 -227.09,-1041.46 -227.09,-1027.78 -227.09,-1022 -193.26,-988.17 -178.76,-988.17 U17.B1@-140.28,-949.68
OSC_32K_OUT: C11.2 U17.C1 Y1.2 | length 161.2
  Top Layer w6: C11.2@-143.81,-1074.68 -170,-1048.49 -170,-1041.46 -170,-1010.91 U17.C1@-108.78,-949.68
PINA: E1.10 U17.B9 | length 1070.4
  Top Layer w4: E1.10@-275.59,-1449.8 -273.54,-1447.76 -273.54,-1385.21 -267.02,-1378.69 -256.24,-1378.69 -249.5,-1371.95 -249.5,-1360.59 -302.43,-1307.66 -302.43,-1196.57 -415,-1084 -415,-891.37 -380.41,-856.77 -380.41,-847.14 -315.27,-782 -315.27,-741.2 -316.89,-739.58 -316.89,-693.86 -306.53,-683.5 -167.08,-683.5 -157.11,-693.47 -147.7,-693.47 -143.45,-697.72 U17.B9@-140.28,-697.72
PINB: E1.55 U17.A8 | length 1380.3
  Top Layer w4: v3(-305,-735) -305,-810.53 -292.04,-823.49 -292.04,-844.45 -314.09,-866.5 -314.09,-877.7 -330.01,-893.62 -338.53,-893.62 -362.5,-917.59 -362.5,-1062.25 -249.93,-1174.82 -249.93,-1175.07 -249.04,-1175.96 -249.04,-1258.59 -224,-1283.63 v3(-224,-1306.19) ; v3(-259.93,-732.86) -259.93,-734.74 -248.85,-745.82 -214.93,-745.82 -198.32,-729.21 U17.A8@-171.77,-729.21
  Signal Layer 1 w4: v3(-305,-735) -305,-732.86 -304.39,-733.47 -299.26,-733.47 -298.66,-732.86 v3(-259.93,-732.86) v3@-259.93,-733.13 ; v3(-224,-1306.19) -224,-1305.3 -217.66,-1298.96 -17.46,-1298.96 -0.05,-1281.54 41.47,-1281.54 54.78,-1268.24 v1(54.78,-1267.46)
  Bottom Layer w4: v1(54.78,-1267.46) 58.52,-1267.46 75.5,-1284.44 75.5,-1313.22 66.72,-1321.99 66.72,-1344.48 95.71,-1373.46 127.6,-1373.46 167.32,-1413.19 E1.55@167.32,-1459.65
PINC: E1.46 U17.C9 | length 1551.3
  Top Layer w4: v3(-197,-1325.19) -197,-1289.46 -201.5,-1284.96 -201.5,-1284.7 -233.25,-1252.96 -233.25,-1169.75 -347.5,-1055.5 -347.5,-923.8 -332.32,-908.62 -320.31,-908.62 -314.5,-902.81 -306.68,-902.81 -284.54,-880.67 -284.54,-820.38 -292.39,-812.54 -292.39,-705.24 -289.17,-702.02 -186.38,-702.02 -174.94,-713.46 -124.52,-713.46 U17.C9@-108.78,-697.72 ; E1.46@78.74,-1449.8 83.36,-1445.19 83.36,-1401.61 89.03,-1395.94 v3(87.61,-1395.94)
  Signal Layer 1 w4: v3(-197,-1325.19) -268.75,-1325.19 -290,-1346.44 -290,-1360.8 -270.46,-1380.34 -251.12,-1380.34 -226.5,-1404.96 -189.18,-1404.96 -177.26,-1393.04 -159.9,-1393.04 -125.82,-1358.96 -54.24,-1358.96 -37.82,-1375.38 -37.82,-1401.06 -29.88,-1409 74.54,-1409 v3(87.61,-1395.94)
PIND: E1.70 U17.D9 | length 1572.8
  Top Layer w4: U17.D9@-77.28,-697.72 -63.54,-683.98 v3(-63.54,-682.34) ; v3(239.37,-560.64) 240.9,-559.11 246.55,-559.11 259.45,-546.22 332.18,-546.22 483.5,-697.54 483.5,-751.62 496.41,-764.53 496.41,-813.76 501.79,-819.13 501.79,-861.56 521.5,-881.27 521.5,-1100.03 505.5,-1116.03 505.5,-1163.81 314.96,-1354.35 E1.70@314.96,-1449.8
  Signal Layer 1 w4: v3(-63.54,-682.34) -72,-673.88 -72,-651.17 -58.91,-638.08 -54.5,-638.08 -42.17,-625.75 15.72,-625.75 68.12,-573.35 182.02,-573.35 197.02,-558.35 227.74,-558.35 230.03,-560.64 v3(239.37,-560.64)
PINE: E1.62 U17.H4 | length 1196.4
  Top Layer w4: U17.H4@48.7,-855.2 50.48,-855.2 63.35,-842.32 v3(65.13,-842.32) ; E1.62@236.22,-1449.8 236.22,-1390.66 475.5,-1151.38 475.5,-1103.6 491.5,-1087.6 491.5,-908.69 480.2,-897.39 480.2,-889.78 484.62,-885.35 v3(484.62,-883.43)
  Signal Layer 1 w4: v3(65.13,-842.32) 84.5,-861.69 170.33,-861.69 178.82,-853.2 178.82,-833.84 206.18,-806.48 295.93,-806.48 302.46,-813.01 329.67,-813.01 345.67,-829.01 434.25,-829.01 461.5,-856.26 461.5,-860.31 v3(484.62,-883.43)
PINF: E1.64 U17.H3 | length 1230.1
  Top Layer w4: U17.H3@48.7,-886.69 51.5,-886.69 64,-874.2 v3(64,-872.19) ; E1.64@255.91,-1449.8 259.91,-1445.8 259.91,-1402.14 275.59,-1386.46 275.59,-1361.9 483,-1154.49 483,-1106.71 499,-1090.71 499,-902.09 498.4,-901.5 495,-898.09 v3(495,-895.93)
  Signal Layer 1 w4: v3(64,-872.19) 66.16,-872.19 69.16,-869.19 173.43,-869.19 186.32,-856.31 186.32,-836.95 209.29,-813.98 292.82,-813.98 303.95,-825.11 303.95,-840.85 290.79,-854.01 290.79,-863.66 297.53,-870.39 307.76,-870.39 317.91,-860.25 445.18,-860.25 482.49,-897.57 488.66,-897.57 488.76,-897.46 493.47,-897.46 v3(495,-895.93)
PING: E1.66 U17.M12 | length 1229.6
  Top Layer w4: U17.M12@174.69,-603.23 177.86,-603.23 180.11,-605.48 221.4,-605.48 265.66,-561.22 325.96,-561.22 468.5,-703.75 468.5,-757.83 481.41,-770.75 481.41,-819.97 486.79,-825.35 486.79,-867.77 506.5,-887.48 506.5,-1093.82 490.5,-1109.82 490.5,-1157.6 283.09,-1365 283.09,-1389.56 275.59,-1397.06 E1.66@275.59,-1449.8
PINH: E1.68 U17.M11 | length 1274.1
  Top Layer w4: U17.M11@174.69,-634.72 175.81,-633.6 190.47,-633.6 195.97,-628.1 v3(196.81,-628.1) ; v3(200.5,-592.35) 202.03,-593.88 207.93,-593.88 210.39,-596.35 219.92,-596.35 262.55,-553.72 329.07,-553.72 476,-700.65 476,-754.73 488.91,-767.64 488.91,-816.86 494.29,-822.24 494.29,-864.67 514,-884.38 514,-1096.92 498,-1112.92 498,-1160.7 307.46,-1351.24 307.46,-1392.71 298.31,-1401.85 298.31,-1446.76 E1.68@295.28,-1449.8
  Signal Layer 1 w4: v3(196.81,-628.1) 198.16,-628.1 200.5,-625.76 v3(200.5,-592.35)
PINJ: E1.54 U17.G12 | length 1435.7
  Top Layer w4: U17.G12@17.2,-603.23 19.11,-601.32 v3(19.11,-585.46) ; E1.54@157.48,-1449.8 161.7,-1445.58 161.7,-1393.23 175.24,-1379.69 204.77,-1379.69 445.5,-1138.96 445.5,-1090.72 461.5,-1074.72 461.5,-921.12 450.2,-909.82 450.2,-866.32 456.79,-859.73 456.79,-837.77 449.76,-830.74 449.76,-781.52 438.5,-770.26 438.5,-716.75 342.94,-621.19 v3(323,-621.19)
  Signal Layer 1 w4: v3(19.11,-585.46) v3(19.11,-585.46) 34.87,-585.39 61.91,-558.35 175.81,-558.35 192.52,-541.64 250.59,-541.64 261.64,-552.69 281.46,-552.69 283.64,-554.87 311.38,-582.61 311.38,-609.57 v3(323,-621.19)
PINK: E1.56 U17.F12 | length 1467.3
  Top Layer w4: U17.F12@-14.29,-603.23 v3(-14.29,-585.46) ; E1.56@177.17,-1461.61 181.14,-1457.64 181.14,-1413.92 453,-1142.06 453,-1093.83 469,-1077.83 469,-918.01 457.7,-906.71 457.7,-869.43 464.29,-862.83 464.29,-834.67 457.26,-827.63 457.26,-778.41 446,-767.15 446,-713.64 320.36,-588 v3(298,-588)
  Signal Layer 1 w4: v3(-14.29,-585.46) -14.29,-587.62 -10.97,-590.94 -10.97,-591.11 2.46,-604.53 26.33,-604.53 65.02,-565.85 178.92,-565.85 195.63,-549.14 247.49,-549.14 257.93,-559.58 257.93,-559.76 258.36,-560.19 278.35,-560.19 297.39,-579.23 297.39,-585.09 297.17,-585.31 298,-586.14 v3(298,-588)
PINL: E1.34 U17.C4 | length 1158.4
  Top Layer w4: v1(-315.36,-851.5) -316.86,-853 -321.92,-853 -377.5,-908.58 -377.5,-1068.47 -264.93,-1181.03 -264.93,-1292.13 -223.2,-1333.85 -216.64,-1333.85 -206.31,-1344.19 -189.13,-1344.19 -180.9,-1335.96 -145.46,-1335.96 -129.28,-1352.14 -87.76,-1352.14 -61.11,-1378.8 -47.36,-1378.8 -42,-1384.16 -42,-1447.17 E1.34@-39.37,-1449.8 ; U17.C4@-108.78,-855.2 -108.78,-856.74 -96.95,-868.57 v1(-96.95,-870.12)
  Bottom Layer w4: v1(-315.36,-851.5) -314.5,-852.36 -314.5,-876.02 -307.76,-882.76 -304.45,-882.76 -269.23,-917.98 -130.57,-917.98 -96.95,-884.36 v1(-96.95,-870.12)
PINM: E1.36 U17.C3 | length 1042.8
  Top Layer w4: v3@-325.62,-872.93 -334.09,-881.4 -336.92,-881.4 -370,-914.48 -370,-1065.36 -257.43,-1177.93 -257.43,-1289.02 -220.1,-1326.35 -213.54,-1326.35 -203.2,-1336.69 -192.24,-1336.69 -184,-1328.46 -142.36,-1328.46 -126.17,-1344.64 -84.66,-1344.64 -69.13,-1360.17 -58,-1371.3 -44.26,-1371.3 -34.5,-1381.05 -34.5,-1389.95 -22.6,-1401.85 -22.6,-1420.33 E1.36@-19.68,-1423.25 ; v1(-123.85,-895) -122.93,-895 -116.87,-888.94 -111.03,-888.94 U17.C3@-108.78,-886.69
  Signal Layer 1 w4: v3(-325.59,-872.93) -306.43,-872.93 -304.76,-871.26 v1(-302.59,-871.26)
  Bottom Layer w4: v1(-302.59,-871.26) -302.59,-871.67 -263.78,-910.48 -139.33,-910.48 v1(-123.85,-895)
PINN: E1.41 U17.L2 | length 839
  Top Layer w4: v1(139,-1106) v1@139,-1106.38 ; U17.L2@143.19,-918.19 158.21,-933.21 185.56,-933.21 239.02,-986.67 239.02,-1071.44 220.86,-1089.6 202.3,-1089.6 183.45,-1108.45 146.32,-1108.45 145.01,-1107.14 139.76,-1107.14 v1@139,-1106.38 ; v1@139,-1106.38 139,-1107.22 138.2,-1106.42 138.62,-1106 v1@139,-1106.38
  Bottom Layer w4: E1.41@29.53,-1459.65 29.53,-1396.03 22.78,-1389.28 22.78,-1368.31 -31.79,-1313.74 -31.79,-1274.38 4.55,-1238.04 4.55,-1137.07 36.48,-1105.15 70.66,-1105.15 76.78,-1111.27 128.47,-1111.27 129.24,-1110.5 129.43,-1110.5 v1@133.93,-1106
PINP: E1.58 U17.D10 | length 1503.8
  Top Layer w4: U17.D10@-77.28,-666.22 v3@-64.03,-652.97 ; E1.58@196.85,-1449.8 201.74,-1444.91 201.74,-1403.93 460.5,-1145.17 460.5,-1097.39 476.5,-1081.39 476.5,-914.91 465.2,-903.6 465.2,-872.53 471.79,-865.94 471.79,-831.56 464.76,-824.53 464.76,-775.3 453.5,-764.05 453.5,-709.97 319.75,-576.22 289.03,-576.22 v3(281.78,-583.47)
  Signal Layer 1 w4: v3(-58.16,-653.59) -37.82,-633.25 18.83,-633.25 71.23,-580.85 185.13,-580.85 200.13,-565.85 224.63,-565.85 230.93,-572.14 255.78,-572.14 260.24,-567.69 269.76,-567.69 v3@280.8,-578.72
PINQ: E1.60 U17.E10 | length 1489.3
  Top Layer w4: U17.E10@-45.79,-666.22 -32.49,-679.51 v3(-31.79,-679.51) ; E1.60@216.54,-1449.8 216.54,-1399.74 468,-1148.28 468,-1100.5 484,-1084.5 484,-911.8 472.7,-900.5 472.7,-875.64 479.29,-869.05 479.29,-828.45 472.26,-821.42 472.26,-772.2 461,-760.94 461,-706.86 322.86,-568.72 275.47,-568.72 v3(265,-579.19)
  Signal Layer 1 w4: v3(-31.79,-679.51) -1.73,-649.46 13.23,-649.46 74.34,-588.35 188.24,-588.35 203.24,-573.35 221.53,-573.35 227.82,-579.64 264.55,-579.64 v3(265,-579.19)
PINR: E1.35 U17.D6 | length 1595.4
  Top Layer w4: v1(-391.91,-852.01) -390.37,-850.48 -390.37,-846.5 -338.8,-794.92 -338.8,-757.53 v1(-327,-745.73) ; U17.D6@-77.28,-792.2 -77.28,-789.27 -65,-776.99 v1(-65,-776.19)
  Bottom Layer w4: v1(-391.91,-852.01) -418.56,-852.01 -420.65,-854.1 -456.67,-854.1 -542.5,-939.93 -542.5,-1275.2 -529.2,-1288.5 -343.12,-1288.5 -335.62,-1296 -295.96,-1296 -250.6,-1341.35 -214.34,-1341.35 -210.93,-1344.76 -80.35,-1344.76 -29.53,-1395.59 E1.35@-29.53,-1459.65 ; v1(-327,-745.73) -326.77,-745.96 -315.22,-745.96 -290.51,-770.67 -288.9,-770.67 -277.87,-781.69 -256.63,-781.69 -253.12,-778.18 -140.8,-778.18 -130.87,-788.11 -125.33,-793.65 -82.46,-793.65 v1(-65,-776.19)
PINS: E1.37 U17.M9 | length 1288.1
  Top Layer w4: v3(62.97,-1359.95) 63.46,-1359.46 93.69,-1359.46 101.16,-1351.98 116.3,-1351.98 123.72,-1344.57 136.11,-1344.57 153.49,-1327.19 183.02,-1327.19 391.5,-1118.71 391.5,-1048.43 393,-1046.93 393,-937.47 388.79,-933.26 388.79,-811.99 385,-808.2 385,-726.89 341.3,-683.19 298.13,-683.19 294.13,-687.19 262.37,-687.19 257.75,-682.56 189.84,-682.56 U17.M9@174.69,-697.72
  Signal Layer 1 w4: v1(-23,-1385.19) -17.5,-1390.69 -17.5,-1392.13 -8.13,-1401.5 59.76,-1401.5 75.96,-1385.31 75.96,-1369.96 68.94,-1362.94 68.12,-1362.94 65.13,-1359.95 v3(62.97,-1359.95)
  Bottom Layer w4: v1(-23,-1385.19) -9.84,-1398.35 E1.37@-9.84,-1459.65
PINT: E1.32 U17.C5 | length 1116.1
  Top Layer w4: v1(-303.64,-830.69) -304.44,-831.49 -311.81,-831.49 -329.46,-849.14 -329.46,-849.93 -385,-905.47 -385,-1071.57 -272.43,-1184.14 -272.43,-1295.23 -226.31,-1341.35 -219.75,-1341.35 -209.42,-1351.69 -186.02,-1351.69 -177.79,-1343.46 -148.57,-1343.46 -132.38,-1359.64 -90.87,-1359.64 -66,-1384.51 -66,-1396.45 -59.05,-1403.39 E1.32@-59.05,-1449.8 ; U17.C5@-108.78,-823.7 -106.88,-823.7 -95.83,-812.65 v1(-93.93,-812.65)
  Bottom Layer w4: v1(-303.64,-830.69) -303.54,-830.69 -289.12,-845.11 -126.39,-845.11 v1(-93.93,-812.65)
PINU: E1.22 U17.B5 | length 1046
  Top Layer w4: v1(-315,-819) -315,-821.16 -318.36,-824.53 -318.36,-824.61 -336.96,-843.21 -336.96,-846.82 -392.5,-902.36 -392.5,-1074.68 -279.93,-1187.25 -279.93,-1298.34 -229.42,-1348.85 -222.86,-1348.85 -212.52,-1359.19 -182.92,-1359.19 -176.51,-1352.78 -156.53,-1352.78 -148.96,-1360.35 -148.96,-1371.45 -157.48,-1379.97 E1.22@-157.48,-1449.8 ; U17.B5@-140.28,-823.7 -139.7,-823.7 -130.18,-814.18 -124.27,-814.18 v1(-122.74,-812.65)
  Bottom Layer w4: v1(-315,-819) -314.81,-819.19 -298.88,-819.19 -280.46,-837.61 -145.47,-837.61 -124.37,-816.52 -124.37,-816.44 -124.27,-816.34 v1@-124.27,-812.75
PINV: E1.40 U17.H1 | length 995.5
  Top Layer w4: E1.40@19.69,-1449.8 22.78,-1446.71 22.78,-1314.06 36.53,-1300.31 36.53,-1297.56 43.91,-1290.19 44.87,-1290.19 46.3,-1288.76 127.28,-1288.76 133.85,-1282.19 164.38,-1282.19 346.5,-1100.07 346.5,-1029.79 348,-1028.29 348,-978.82 340.7,-971.51 v3(340.5,-971.51) ; U17.H1@48.7,-949.68 48.91,-949.68 64,-934.59 v3(64,-933.19)
  Signal Layer 1 w4: v3@66.49,-934.87 67.52,-934.87 70.34,-937.69 95.53,-937.69 98.03,-940.19 242.57,-940.19 260,-957.62 316.65,-957.62 330.55,-971.51 v3(340.5,-971.51)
